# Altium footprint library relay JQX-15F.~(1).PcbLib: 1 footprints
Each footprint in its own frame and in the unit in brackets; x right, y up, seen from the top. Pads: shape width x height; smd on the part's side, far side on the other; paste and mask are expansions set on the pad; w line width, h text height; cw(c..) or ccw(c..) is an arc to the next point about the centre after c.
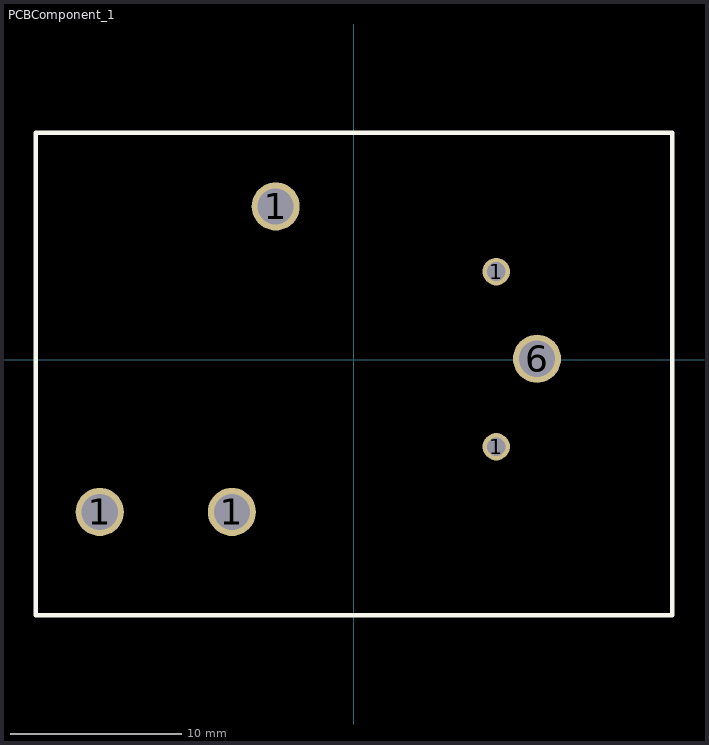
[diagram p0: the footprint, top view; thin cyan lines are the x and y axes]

## PCBComponent_1 [mm]
pads (6):
  round 2.8 hole 2.1: 1(-14.8,-8.875) 1(-7.1,-8.875) 1(-4.55,8.925) 6(10.675,0.05)
  round 1.6 hole 1.1: 1(8.3,-5.075) 1(8.3,5.125)
Top Overlay:
  lines w0.254: -18.525,-14.9 -15.125,-14.9 18.55,-14.9 18.55,13.225 -18.525,13.225 -18.525,-14.9
3D body: height 20.4, standoff 0, extent -18.525,-14.875 18.5,13.15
